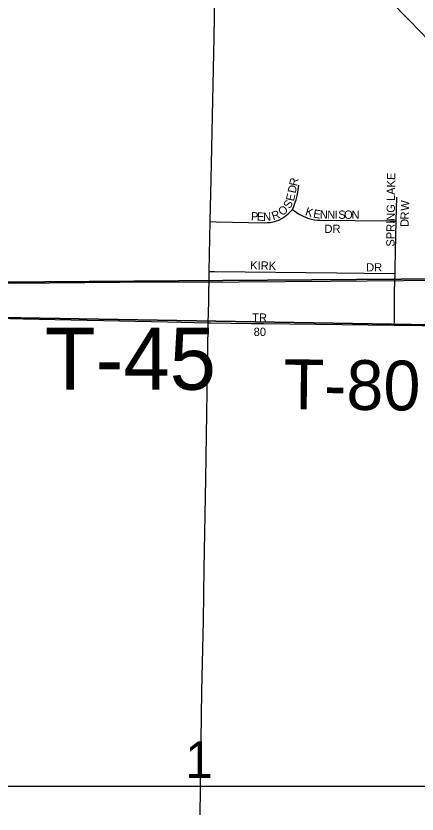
# Model space of a CAD drawing. Extents: x 0 to 68, y 0 to 52.9.
# Drawn here: x 43.122 to 43.605, y 34.705 to 35.667 of the extents above; entities that cross this region are included whole.
import ezdxf

# ---------------------------------------------------------------- set-up
doc = ezdxf.new("R2010")
doc.units = 0
for name, color, linetype in [('Default', 7, 'Continuous'), ('GM_X_Township_Road', 7, 'Continuous'), ('GM_X_Township_Road_Text', 7, 'Continuous')]:
    doc.layers.add(name, color=color, linetype=linetype)

msp = doc.modelspace()

# ---------------------------------------------------------------- linework, layer by layer
at = {"layer": 'Default'}
msp.add_line((42.25806, 34.73908), (49.65006, 34.73908), dxfattribs=at)
for points in [[(43.11555, 36.67874), (44.34414, 36.66665), (44.32023, 35.33817), (43.69327, 35.3509), (43.1026, 35.34663), (43.11455, 36.64024)], [(42.83718, 36.36115), (43.90273, 36.34073), (43.8802, 35.29067), (42.82102, 35.30893)], [(43.1026, 35.34663), (43.69327, 35.3509), (44.32023, 35.33817), (44.30324, 34.00462), (43.08734, 34.03057), (43.1022, 35.31613)], [(42.82102, 35.30893), (43.8802, 35.29067), (43.86646, 34.27144), (43.86565, 34.24064), (42.80414, 34.29415)]]:
    msp.add_lwpolyline(points, close=True, dxfattribs=at)
for points in [[(43.6188, 35.63846), (43.59707, 35.66061), (43.59181, 35.66602), (43.50792, 35.75237)], [(43.45472, 35.43402), (43.45649, 35.43763), (43.45821, 35.44283), (43.45919, 35.44598), (43.46038, 35.45062), (43.46124, 35.45525), (43.46263, 35.46346)], [(43.57997, 35.42054), (43.58052, 35.44888)], [(43.35578, 35.41954), (43.36306, 35.41944), (43.42142, 35.41818), (43.42473, 35.41836), (43.42777, 35.41854), (43.43045, 35.41899), (43.43305, 35.41962), (43.43561, 35.42039), (43.43859, 35.42141), (43.44202, 35.42331), (43.44436, 35.42485), (43.44948, 35.42901), (43.45472, 35.43402)], [(43.45472, 35.43402), (43.46228, 35.4291), (43.46685, 35.42648), (43.47129, 35.42445), (43.47455, 35.42335), (43.47775, 35.42247), (43.48134, 35.42174), (43.48483, 35.42138), (43.48778, 35.42116), (43.57312, 35.4206), (43.57997, 35.42054)], [(43.57843, 35.35705), (43.57855, 35.36289), (43.57962, 35.40256), (43.57997, 35.42054)], [(43.35457, 35.3593), (43.36082, 35.35924), (43.50821, 35.35768), (43.54121, 35.35735), (43.57843, 35.35705)], [(43.5776, 35.2948), (43.57765, 35.3001), (43.57799, 35.33646), (43.57843, 35.35705)], [(43.40559, 35.29692), (43.40583, 35.29692), (43.42029, 35.29674)]]:
    msp.add_lwpolyline(points, dxfattribs=at)
at = {"layer": 'GM_X_Township_Road'}
for points in [[(43.35578, 35.41954), (43.35681, 35.47086), (43.36052, 35.64163), (43.36141, 35.69091), (43.36368, 35.80253), (43.36545, 35.87789), (43.36613, 35.91736), (43.36524, 35.93057), (43.36347, 35.94035), (43.36292, 35.94233), (43.35993, 35.95308), (43.35125, 35.97795), (43.33771, 36.01148), (43.33409, 36.02044)], [(43.35457, 35.3593), (43.35578, 35.41954)], [(43.35323, 35.29766), (43.35385, 35.32306), (43.35457, 35.3593)], [(43.10625, 35.34577), (43.11563, 35.34557), (43.11973, 35.34548), (43.24691, 35.3466), (43.39051, 35.34699), (43.50127, 35.34778), (43.63254, 35.34888), (43.74739, 35.34771), (43.99351, 35.34314), (44.06735, 35.34196), (44.22732, 35.33899), (44.46523, 35.33417), (44.78106, 35.32815), (44.99612, 35.32175)], [(42.82308, 35.30921), (42.90725, 35.30749), (43.00566, 35.30543), (43.1303, 35.30244), (43.30419, 35.29888), (43.35323, 35.29766)], [(43.34347, 34.70427), (43.34573, 34.85344), (43.34759, 34.93881), (43.34856, 35.00123), (43.35027, 35.10961), (43.35313, 35.29355), (43.35323, 35.29766)], [(43.35323, 35.29766), (43.35662, 35.29757), (43.40559, 35.29692)], [(43.42029, 35.29674), (43.5776, 35.2948)], [(43.5776, 35.2948), (43.64503, 35.29397), (43.72147, 35.29203)]]:
    msp.add_lwpolyline(points, dxfattribs=at)

# ---------------------------------------------------------------- texts
at = {"layer": 'Default'}
for s, height, rotation, p in [('SPRING LAKE', 0.01, 89.3644, (43.57782, 35.38935)), ('D', 0.01, 78.33424, (43.45861, 35.45319)), ('R', 0.01, 77.74244, (43.46038, 35.46179)), ('E', 0.01, 77.54566, (43.45653, 35.44356)), ('S', 0.01, 58.68266, (43.45154, 35.43422)), ('W', 0.01, 87.98219, (43.59528, 35.4324)), ('O', 0.01, 41.16185, (43.44277, 35.42589)), ('K', 0.01, 342.34609, (43.46942, 35.42761)), ('E', 0.01, 350.61306, (43.47934, 35.42458)), ('P', 0.01, 357.07482, (43.40468, 35.42118)), ('E', 0.01, 357.08717, (43.41171, 35.42082)), ('N', 0.01, 0.98462, (43.41948, 35.42046)), ('R', 0.01, 19.0462, (43.43166, 35.4212)), ('N', 0.01, 357.86488, (43.48766, 35.42329)), ('N', 0.01, 359.92533, (43.49684, 35.42295)), ('I', 0.01, 359.985, (43.50565, 35.42294)), ('S', 0.01, 359.99563, (43.51006, 35.42294)), ('O', 0.01, 359.99285, (43.5171, 35.42294)), ('N', 0.01, 359.99285, (43.52589, 35.42294)), ('R', 0.01, 88.27532, (43.59495, 35.42186)), ('DR', 0.01, 0.00001, (43.49346, 35.40593)), ('D', 0.01, 89.19122, (43.59483, 35.41311)), ('KIRK', 0.01, 358.31626, (43.40375, 35.3621)), ('DR', 0.01, 0.00001, (43.54362, 35.35946)), ('TR', 0.01, 0.00001, (43.40634, 35.29884)), ('80', 0.01, 0.00001, (43.4081, 35.28168)), ('1', 0.0442, 0.00001, (43.32582, 34.74881))]:
    msp.add_text(s, height=height, rotation=rotation, dxfattribs=at).set_placement(p)
at = {"layer": 'GM_X_Township_Road_Text'}
for s, height, rotation, p in [('T-45', 0.075, 0.00001, (43.1564, 35.21691)), ('T-80', 0.06, 359.29306, (43.44377, 35.19373))]:
    msp.add_text(s, height=height, rotation=rotation, dxfattribs=at).set_placement(p)

doc.saveas('drawing.dxf')
